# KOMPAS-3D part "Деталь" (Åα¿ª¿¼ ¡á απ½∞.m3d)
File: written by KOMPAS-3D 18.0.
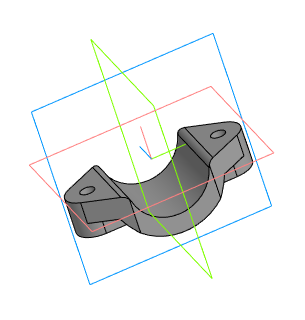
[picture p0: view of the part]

Document properties: Автор: Пользователь Windows; Полное имя файла: F:\Модели\Мех детали\Велосипед\Крепление фонаря\2\Прижим на руль.m3d

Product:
- Part/product: Деталь
    Масса: 0.0529721

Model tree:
1. Эскиз:1
2. Элемент выдавливания:1
     Расстояние 1 = 25
3. Эскиз:2  (with: Элемент выдавливания:1)
4. Элемент выдавливания:2
     Расстояние 2 = 10
5. Эскиз:3  (with: Элемент выдавливания:1, Элемент выдавливания:2)
6. Элемент выдавливания:3
     Расстояние 1 = 5
7. Эскиз:4
8. Элемент выдавливания:7
     Расстояние 1 = 20
9. Эскиз:5  (with: Элемент выдавливания:1)
10. Элемент выдавливания:8
     Расстояние 2 = 25
11. Элемент выдавливания:9  (with: Элемент выдавливания:3, Элемент выдавливания:1)
     Расстояние 1 = 5
12. Элемент выдавливания:10  (with: Элемент выдавливания:3, Элемент выдавливания:1)
     Расстояние 1 = 5
13. Скругление:2  (with: Элемент выдавливания:1)
     Радиус = 2
14. Эскиз:6  (with: Элемент выдавливания:3)
15. Элемент выдавливания:13
     Расстояние 2 = 10
16. Эскиз:8  (with: Элемент выдавливания:13)
17. Элемент выдавливания:14
     Расстояние 2 = 50
18. Булева операция:3
19. Булева операция:4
